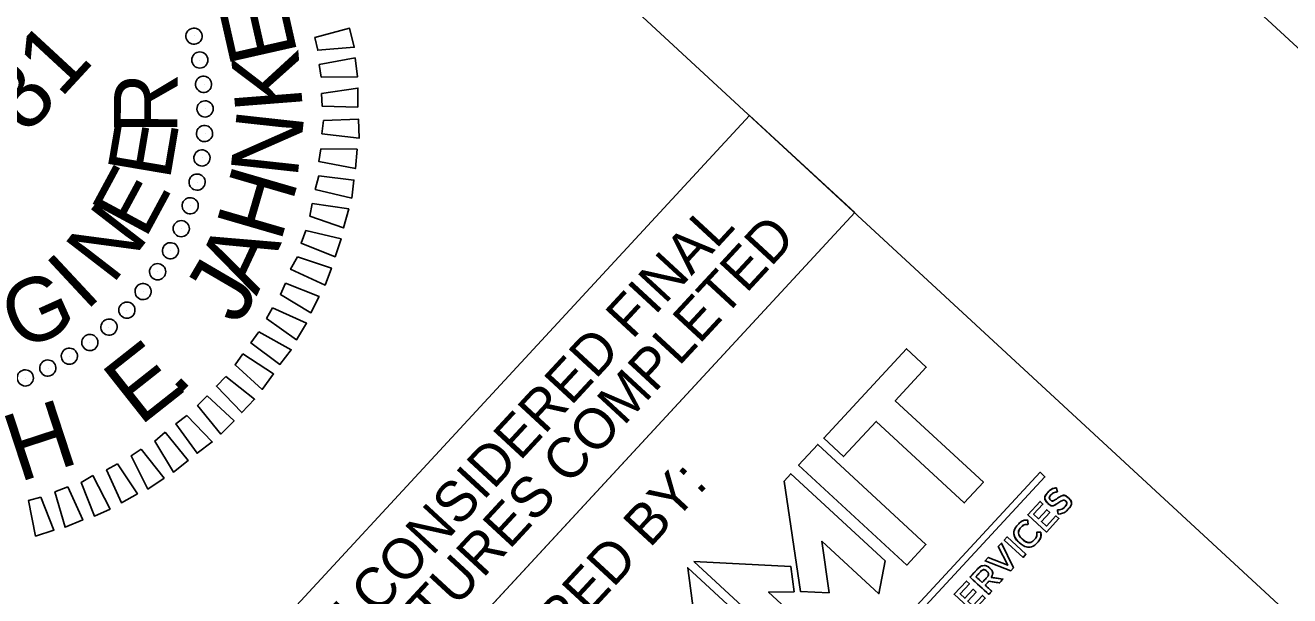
# Model space of a CAD drawing. Extents: x 1768064 to 1770025, y 999327 to 1001342.
# Drawn here: x 1769319.3 to 1769431.7, y 1001074.7 to 1001125.4 of the extents above; entities that cross this region are included whole.
import ezdxf

# ---------------------------------------------------------------- set-up
doc = ezdxf.new("R2010")
doc.units = 0
for name, color, linetype in [('_CIVIL_CONSTRUCTION', 7, 'Continuous'), ('E_NCDOT_Terrain_Model_Flow_Arrows', 7, 'Continuous'), ('E_NCDOT_Terrain_Model_Spot_Elevation', 7, 'Continuous'), ('P_NCDOT_Horizontal_Alignment_Station_Major_Label', 7, 'Continuous'), ('P_NCDOT_Horizontal_Alignment_Tick_Large', 7, 'Continuous')]:
    doc.layers.add(name, color=color, linetype=linetype)

msp = doc.modelspace()

# ---------------------------------------------------------------- linework, layer by layer
at = {"layer": '_CIVIL_CONSTRUCTION'}
msp.add_lwpolyline([(1768063.72, 1000073.53), (1769217.66, 1001321.9), (1770025.42, 1000575.24), (1768871.49, 999326.87)], close=True, dxfattribs=at)
at = {"layer": 'E_NCDOT_Terrain_Model_Flow_Arrows'}
msp.add_line((1770025.42, 1000575.24), (1769217.66, 1001321.9), dxfattribs=at)
at = {"layer": 'E_NCDOT_Terrain_Model_Spot_Elevation'}
msp.add_line((1769972.42, 1000573.14), (1769219.74, 1001268.91), dxfattribs=at)
at = {"layer": 'P_NCDOT_Horizontal_Alignment_Station_Major_Label'}
for p, q in [((1769393.04, 1001108.72), (1769325.2, 1001035.33)), ((1769411.06, 1001083.89), (1769410.97, 1001084.25)), ((1769410.45, 1001083.17), (1769410.44, 1001083.17)), ((1769411.79, 1001083.06), (1769411.79, 1001083.06)), ((1769412.03, 1001083.36), (1769412.02, 1001083.37)), ((1769410.21, 1001082.87), (1769410.21, 1001082.86)), ((1769411.06, 1001082.28), (1769411.11, 1001081.91)), ((1769408.46, 1001081), (1769408.41, 1001081.38)), ((1769407.94, 1001079.67), (1769407.94, 1001079.67)), ((1769409.59, 1001080.31), (1769409.23, 1001080.31)), ((1769407.67, 1001079.37), (1769407.67, 1001079.37)), ((1769404.78, 1001076.83), (1769404.78, 1001076.82)), ((1769405.03, 1001077.12), (1769405.02, 1001077.13))]:
    msp.add_line(p, q, dxfattribs=at)
msp.add_lwpolyline([(1769315.85, 1001043.97), (1769383.69, 1001117.36), (1769393.04, 1001108.72), (1769325.2, 1001035.33)], close=True, dxfattribs=at)
for points in [[(1769397.63, 1001096.61), (1769399.4, 1001094.97), (1769396.65, 1001091.99), (1769404.48, 1001084.75), (1769402.78, 1001082.91), (1769394.95, 1001090.15), (1769392.06, 1001087.03), (1769390.29, 1001088.67), (1769397.63, 1001096.61)], [(1769390.29, 1001088.67), (1769392.06, 1001087.03), (1769394.95, 1001090.15), (1769402.78, 1001082.91), (1769404.48, 1001084.75), (1769396.65, 1001091.99), (1769399.4, 1001094.97), (1769397.63, 1001096.61), (1769390.29, 1001088.67)], [(1769388.06, 1001086.26), (1769389.76, 1001088.1), (1769399.37, 1001079.22), (1769397.67, 1001077.38), (1769388.06, 1001086.26)], [(1769397.67, 1001077.38), (1769399.37, 1001079.22), (1769389.76, 1001088.1), (1769388.06, 1001086.26), (1769397.67, 1001077.38)], [(1769409.95, 1001085.22), (1769368.67, 1001040.57), (1769368.23, 1001040.98), (1769409.51, 1001085.63), (1769409.95, 1001085.22)], [(1769409.51, 1001085.63), (1769368.23, 1001040.98), (1769368.67, 1001040.57), (1769409.95, 1001085.22), (1769409.51, 1001085.63)], [(1769386.76, 1001084.85), (1769388.23, 1001075.02), (1769390.77, 1001074.91), (1769390.13, 1001079.5), (1769395.2, 1001074.82), (1769395.74, 1001077.76), (1769387.36, 1001085.5), (1769386.76, 1001084.85)], [(1769386.76, 1001084.85), (1769388.23, 1001075.02), (1769390.77, 1001074.91), (1769390.13, 1001079.5), (1769395.2, 1001074.82), (1769395.74, 1001077.76), (1769387.36, 1001085.5), (1769386.76, 1001084.85)], [(1769408.42, 1001081.85), (1769409.51, 1001083.04), (1769409.77, 1001082.8), (1769408.94, 1001081.89), (1769409.37, 1001081.49), (1769410.11, 1001082.29), (1769410.37, 1001082.05), (1769409.63, 1001081.25), (1769410.08, 1001080.84), (1769410.93, 1001081.75), (1769411.19, 1001081.51), (1769410.08, 1001080.31), (1769408.42, 1001081.85)], [(1769410.08, 1001080.31), (1769411.19, 1001081.51), (1769410.93, 1001081.75), (1769410.08, 1001080.84), (1769409.63, 1001081.25), (1769410.37, 1001082.05), (1769410.11, 1001082.29), (1769409.37, 1001081.49), (1769408.94, 1001081.89), (1769409.77, 1001082.8), (1769409.51, 1001083.04), (1769408.42, 1001081.85), (1769410.08, 1001080.31)], [(1769406.33, 1001079.6), (1769406.59, 1001079.88), (1769408.26, 1001078.34), (1769408, 1001078.06), (1769406.33, 1001079.6)], [(1769408, 1001078.06), (1769408.26, 1001078.34), (1769406.59, 1001079.88), (1769406.33, 1001079.6), (1769408, 1001078.06)], [(1769404.63, 1001077.75), (1769404.91, 1001078.06), (1769406.64, 1001077.36), (1769405.8, 1001079.03), (1769406.08, 1001079.33), (1769407.15, 1001077.12), (1769406.92, 1001076.87), (1769404.63, 1001077.75)], [(1769406.92, 1001076.87), (1769407.15, 1001077.12), (1769406.08, 1001079.33), (1769405.8, 1001079.03), (1769406.64, 1001077.36), (1769404.91, 1001078.06), (1769404.63, 1001077.75), (1769406.92, 1001076.87)], [(1769378.74, 1001077.7), (1769390.44, 1001066.89), (1769392.14, 1001068.73), (1769385.39, 1001074.97), (1769387.66, 1001075), (1769387.37, 1001077.25), (1769378.74, 1001077.7)], [(1769378.74, 1001077.7), (1769390.44, 1001066.89), (1769392.14, 1001068.73), (1769385.39, 1001074.97), (1769387.66, 1001075), (1769387.37, 1001077.25), (1769378.74, 1001077.7)], [(1769378.21, 1001077.14), (1769389.91, 1001066.32), (1769388.21, 1001064.48), (1769381.46, 1001070.72), (1769381.62, 1001068.46), (1769379.34, 1001068.57), (1769378.21, 1001077.14)], [(1769379.34, 1001068.57), (1769381.62, 1001068.46), (1769381.46, 1001070.72), (1769388.21, 1001064.48), (1769389.91, 1001066.32), (1769378.21, 1001077.14), (1769379.34, 1001068.57)], [(1769403.95, 1001077.02), (1769403.29, 1001076.31), (1769404.96, 1001074.77), (1769405.22, 1001075.05), (1769404.64, 1001075.59), (1769404.96, 1001075.94), (1769405.91, 1001075.79), (1769406.21, 1001076.13), (1769405.18, 1001076.28)], [(1769404.76, 1001076.24), (1769404.38, 1001075.83), (1769403.82, 1001076.34), (1769404.19, 1001076.75)], [(1769401.88, 1001074.78), (1769402.97, 1001075.96), (1769403.23, 1001075.72), (1769402.4, 1001074.82), (1769402.83, 1001074.42), (1769403.57, 1001075.22), (1769403.83, 1001074.98), (1769403.09, 1001074.17), (1769403.54, 1001073.76), (1769404.39, 1001074.68), (1769404.65, 1001074.43), (1769403.54, 1001073.24), (1769401.88, 1001074.78)], [(1769403.54, 1001073.24), (1769404.65, 1001074.43), (1769404.39, 1001074.68), (1769403.54, 1001073.76), (1769403.09, 1001074.17), (1769403.83, 1001074.98), (1769403.57, 1001075.22), (1769402.83, 1001074.42), (1769402.4, 1001074.82), (1769403.23, 1001075.72), (1769402.97, 1001075.96), (1769401.88, 1001074.78), (1769403.54, 1001073.24)]]:
    msp.add_lwpolyline(points, dxfattribs=at)
for points, degree in [([(1769410.97, 1001084.25), (1769410.69, 1001084.21), (1769410.44, 1001084.09), (1769410.23, 1001083.86), (1769409.93, 1001083.54), (1769409.92, 1001083.13), (1769410.21, 1001082.87)], 3), ([(1769411.11, 1001081.91), (1769411.11, 1001081.91), (1769411.06, 1001082.28), (1769411.06, 1001082.28), (1769411.34, 1001082.3), (1769411.56, 1001082.38), (1769411.74, 1001082.58), (1769411.9, 1001082.75), (1769411.92, 1001082.94), (1769411.79, 1001083.06), (1769411.79, 1001083.06), (1769411.79, 1001083.06), (1769411.79, 1001083.06), (1769411.67, 1001083.17), (1769411.55, 1001083.17), (1769411.2, 1001082.94), (1769410.8, 1001082.68), (1769410.52, 1001082.58), (1769410.21, 1001082.86), (1769410.21, 1001082.86), (1769410.21, 1001082.87), (1769410.21, 1001082.87), (1769409.92, 1001083.13), (1769409.93, 1001083.54), (1769410.23, 1001083.86), (1769410.44, 1001084.09), (1769410.69, 1001084.21), (1769410.97, 1001084.25), (1769410.97, 1001084.25), (1769411.06, 1001083.89), (1769411.06, 1001083.89), (1769410.81, 1001083.85), (1769410.62, 1001083.76), (1769410.48, 1001083.62), (1769410.33, 1001083.45), (1769410.33, 1001083.28), (1769410.44, 1001083.17), (1769410.44, 1001083.17), (1769410.45, 1001083.17), (1769410.45, 1001083.17), (1769410.57, 1001083.05), (1769410.7, 1001083.07), (1769411.06, 1001083.31), (1769411.46, 1001083.57), (1769411.74, 1001083.62), (1769412.02, 1001083.37), (1769412.02, 1001083.37), (1769412.03, 1001083.36), (1769412.03, 1001083.36), (1769412.34, 1001083.08), (1769412.31, 1001082.67), (1769412, 1001082.33), (1769411.77, 1001082.09), (1769411.47, 1001081.94), (1769411.11, 1001081.91)], 3), ([(1769410.21, 1001082.86), (1769410.52, 1001082.58), (1769410.8, 1001082.68), (1769411.2, 1001082.94), (1769411.55, 1001083.17), (1769411.67, 1001083.17), (1769411.79, 1001083.06)], 3), ([(1769410.44, 1001083.17), (1769410.33, 1001083.28), (1769410.33, 1001083.45), (1769410.48, 1001083.62), (1769410.62, 1001083.76), (1769410.81, 1001083.85), (1769411.06, 1001083.89)], 3), ([(1769412.02, 1001083.37), (1769411.74, 1001083.62), (1769411.46, 1001083.57), (1769411.06, 1001083.31), (1769410.7, 1001083.07), (1769410.57, 1001083.05), (1769410.45, 1001083.17)], 3), ([(1769411.79, 1001083.06), (1769411.92, 1001082.94), (1769411.9, 1001082.75), (1769411.74, 1001082.58), (1769411.56, 1001082.38), (1769411.34, 1001082.3), (1769411.06, 1001082.28)], 3), ([(1769411.11, 1001081.91), (1769411.47, 1001081.94), (1769411.77, 1001082.09), (1769412, 1001082.33), (1769412.31, 1001082.67), (1769412.34, 1001083.08), (1769412.03, 1001083.36)], 3), ([(1769407.67, 1001079.37), (1769407.67, 1001079.37), (1769407.67, 1001079.37), (1769407.67, 1001079.37), (1769407.19, 1001079.81), (1769407.12, 1001080.51), (1769407.57, 1001080.99), (1769407.84, 1001081.29), (1769408.11, 1001081.37), (1769408.41, 1001081.38), (1769408.41, 1001081.38), (1769408.46, 1001081), (1769408.46, 1001081), (1769408.21, 1001080.99), (1769408, 1001080.93), (1769407.84, 1001080.74), (1769407.55, 1001080.44), (1769407.61, 1001079.97), (1769407.94, 1001079.67), (1769407.94, 1001079.67), (1769407.94, 1001079.67), (1769407.94, 1001079.67), (1769408.27, 1001079.37), (1769408.74, 1001079.34), (1769409.02, 1001079.65), (1769409.2, 1001079.84), (1769409.24, 1001080.05), (1769409.23, 1001080.31), (1769409.23, 1001080.31), (1769409.59, 1001080.31), (1769409.59, 1001080.31), (1769409.61, 1001079.98), (1769409.56, 1001079.69), (1769409.28, 1001079.39), (1769408.85, 1001078.92), (1769408.15, 1001078.93), (1769407.67, 1001079.37)], 3), ([(1769408.41, 1001081.38), (1769408.11, 1001081.37), (1769407.84, 1001081.29), (1769407.57, 1001080.99), (1769407.12, 1001080.51), (1769407.19, 1001079.81), (1769407.67, 1001079.37)], 3), ([(1769407.94, 1001079.67), (1769407.61, 1001079.97), (1769407.55, 1001080.44), (1769407.84, 1001080.74), (1769408, 1001080.93), (1769408.21, 1001080.99), (1769408.46, 1001081)], 3), ([(1769407.67, 1001079.37), (1769408.15, 1001078.93), (1769408.85, 1001078.92), (1769409.28, 1001079.39), (1769409.56, 1001079.69), (1769409.61, 1001079.98), (1769409.59, 1001080.31)], 3), ([(1769409.23, 1001080.31), (1769409.24, 1001080.05), (1769409.2, 1001079.84), (1769409.02, 1001079.65), (1769408.74, 1001079.34), (1769408.27, 1001079.37), (1769407.94, 1001079.67)], 3), ([(1769403.29, 1001076.31), (1769403.29, 1001076.31), (1769403.95, 1001077.02), (1769403.95, 1001077.02), (1769404.14, 1001077.22), (1769404.34, 1001077.32), (1769404.54, 1001077.33), (1769404.71, 1001077.33), (1769404.88, 1001077.26), (1769405.02, 1001077.13), (1769405.02, 1001077.13), (1769405.03, 1001077.12), (1769405.03, 1001077.12), (1769405.3, 1001076.87), (1769405.32, 1001076.56), (1769405.18, 1001076.28), (1769405.18, 1001076.28), (1769406.21, 1001076.13), (1769406.21, 1001076.13), (1769406.21, 1001076.13), (1769405.91, 1001075.79), (1769405.91, 1001075.79), (1769405.91, 1001075.79), (1769404.96, 1001075.94), (1769404.96, 1001075.94), (1769404.96, 1001075.94), (1769404.64, 1001075.59), (1769404.64, 1001075.59), (1769404.64, 1001075.59), (1769405.22, 1001075.05), (1769405.22, 1001075.05), (1769405.22, 1001075.05), (1769404.96, 1001074.77), (1769404.96, 1001074.77), (1769404.96, 1001074.77), (1769403.29, 1001076.31), (1769403.29, 1001076.31)], 3), ([(1769405.02, 1001077.13), (1769404.88, 1001077.26), (1769404.71, 1001077.33), (1769404.54, 1001077.33), (1769404.34, 1001077.32), (1769404.14, 1001077.22), (1769403.95, 1001077.02)], 3), ([(1769404.76, 1001076.24), (1769404.94, 1001076.44), (1769404.95, 1001076.67), (1769404.78, 1001076.82), (1769404.78, 1001076.82), (1769404.78, 1001076.83), (1769404.78, 1001076.83), (1769404.6, 1001076.99), (1769404.39, 1001076.96), (1769404.19, 1001076.75), (1769404.19, 1001076.75), (1769403.82, 1001076.34), (1769403.82, 1001076.34), (1769403.82, 1001076.34), (1769404.38, 1001075.83), (1769404.38, 1001075.83), (1769404.38, 1001075.83), (1769404.76, 1001076.24), (1769404.76, 1001076.24)], 3), ([(1769404.19, 1001076.75), (1769404.39, 1001076.96), (1769404.6, 1001076.99), (1769404.78, 1001076.83)], 2), ([(1769404.78, 1001076.82), (1769404.95, 1001076.67), (1769404.94, 1001076.44), (1769404.76, 1001076.24)], 2), ([(1769405.18, 1001076.28), (1769405.32, 1001076.56), (1769405.3, 1001076.87), (1769405.03, 1001077.12)], 2)]:
    msp.add_open_spline(points, degree=degree, dxfattribs=at)
at = {"layer": 'P_NCDOT_Horizontal_Alignment_Tick_Large'}
for p, q in [((1769334.38, 1001124.43), (1769334.38, 1001124.43)), ((1769334.85, 1001122.29), (1769334.85, 1001122.29)), ((1769335.22, 1001120.11), (1769335.22, 1001120.11)), ((1769335.34, 1001117.96), (1769335.34, 1001117.96)), ((1769335.32, 1001115.73), (1769335.32, 1001115.73)), ((1769335.05, 1001113.59), (1769335.05, 1001113.59)), ((1769334.6, 1001111.42), (1769334.6, 1001111.42)), ((1769334.01, 1001109.31), (1769334.01, 1001109.31)), ((1769333.24, 1001107.29), (1769333.24, 1001107.29)), ((1769332.26, 1001105.35), (1769332.26, 1001105.35)), ((1769331.06, 1001103.46), (1769331.06, 1001103.46)), ((1769329.82, 1001101.68), (1769329.82, 1001101.68)), ((1769328.36, 1001100.03), (1769328.36, 1001100.03)), ((1769326.76, 1001098.51), (1769326.76, 1001098.51)), ((1769325.04, 1001097.17), (1769325.04, 1001097.17)), ((1769323.29, 1001095.93), (1769323.29, 1001095.93)), ((1769321.35, 1001094.87), (1769321.35, 1001094.87)), ((1769319.33, 1001094.01), (1769319.33, 1001094.01))]:
    msp.add_line(p, q, dxfattribs=at)
for points in [[(1769345.07, 1001124.28), (1769348.15, 1001125.11), (1769348.57, 1001123.43), (1769345.32, 1001123.16)], [(1769345.44, 1001121.89), (1769348.64, 1001122.48), (1769348.85, 1001120.79), (1769345.63, 1001120.77)], [(1769345.65, 1001119.32), (1769348.89, 1001119.8), (1769348.88, 1001118.1), (1769345.7, 1001118.19)], [(1769345.82, 1001116.92), (1769348.93, 1001117.04), (1769348.99, 1001115.34), (1769345.69, 1001115.74)], [(1769345.6, 1001114.4), (1769348.82, 1001114.35), (1769348.67, 1001112.64), (1769345.43, 1001113.26)], [(1769345.41, 1001111.98), (1769348.54, 1001111.61), (1769348.35, 1001110.01), (1769345.1, 1001110.77)], [(1769344.83, 1001109.52), (1769348.07, 1001109.05), (1769347.61, 1001107.36), (1769344.63, 1001108.41)], [(1769344.26, 1001107.13), (1769347.4, 1001106.4), (1769346.86, 1001104.79), (1769343.84, 1001106.01)], [(1769343.53, 1001104.8), (1769346.54, 1001103.78), (1769345.97, 1001102.28), (1769342.9, 1001103.68)], [(1769342.46, 1001102.46), (1769345.44, 1001101.26), (1769344.72, 1001099.82), (1769342, 1001101.45)], [(1769341.31, 1001100.25), (1769344.33, 1001098.88), (1769343.43, 1001097.4), (1769340.78, 1001099.31)], [(1769340.08, 1001098.12), (1769342.97, 1001096.53), (1769341.96, 1001095.22), (1769339.38, 1001097.13)], [(1769338.67, 1001096.15), (1769341.39, 1001094.38), (1769340.39, 1001093), (1769337.97, 1001095.17)], [(1769337.16, 1001094.14), (1769339.71, 1001092.12), (1769338.56, 1001090.94), (1769336.31, 1001093.3)], [(1769335.49, 1001092.42), (1769337.88, 1001090.21), (1769336.72, 1001089.03), (1769334.64, 1001091.57)], [(1769333.69, 1001090.68), (1769335.94, 1001088.33), (1769334.6, 1001087.32), (1769332.72, 1001089.94)], [(1769331.76, 1001089.19), (1769333.81, 1001086.69), (1769332.5, 1001085.65), (1769330.84, 1001088.41)], [(1769329.63, 1001087.69), (1769331.67, 1001085.12), (1769330.23, 1001084.14), (1769328.73, 1001087.09)], [(1769327.52, 1001086.37), (1769329.29, 1001083.72), (1769327.87, 1001082.92), (1769326.55, 1001085.84)], [(1769325.33, 1001085.33), (1769326.87, 1001082.35), (1769325.47, 1001081.73), (1769324.3, 1001084.72)], [(1769323.11, 1001084.32), (1769324.43, 1001081.4), (1769322.86, 1001080.74), (1769321.96, 1001083.89)], [(1769320.7, 1001083.41), (1769321.88, 1001080.49), (1769320.24, 1001079.96), (1769319.62, 1001083.12)]]:
    msp.add_lwpolyline(points, close=True, dxfattribs=at)
for centre, major_axis in [((1769334.32, 1001124.41), (0.691, 0.201)), ((1769334.84, 1001122.29), (0.706, 0.14)), ((1769335.17, 1001120.13), (0.716, 0.078)), ((1769335.31, 1001117.94), (0.72, 0.016)), ((1769335.26, 1001115.75), (0.718, -0.047)), ((1769335.03, 1001113.58), (0.712, -0.11)), ((1769334.6, 1001111.43), (0.699, -0.171)), ((1769333.99, 1001109.33), (0.682, -0.231)), ((1769333.19, 1001107.29), (0.659, -0.29)), ((1769332.23, 1001105.33), (0.631, -0.346)), ((1769331.09, 1001103.46), (0.599, -0.4)), ((1769329.8, 1001101.7), (0.562, -0.451)), ((1769328.36, 1001100.05), (0.52, -0.498)), ((1769326.77, 1001098.54), (0.475, -0.541)), ((1769325.07, 1001097.17), (0.426, -0.581)), ((1769323.25, 1001095.95), (0.374, -0.616)), ((1769321.33, 1001094.9), (0.318, -0.646)), ((1769319.33, 1001094.02), (0.261, -0.671))]:
    msp.add_ellipse(centre, major_axis=major_axis, ratio=0.999708, dxfattribs=at)

# ---------------------------------------------------------------- texts
at = {"layer": 'P_NCDOT_Horizontal_Alignment_Station_Major_Label'}
for s, height, p in [('DOCUMENT NOT CONSIDERED FINAL', 3.5982, (1769323.01, 1001042.99)), ('UNLESS ALL SIGNATURES COMPLETED', 3.5982, (1769324.78, 1001038.05)), ('PLANS PREPARED BY:', 3.5979, (1769344.34, 1001045.84))]:
    msp.add_text(s, height=height, rotation=47.2512, dxfattribs=at).set_placement(p)
at = {"layer": 'P_NCDOT_Horizontal_Alignment_Tick_Large'}
for s, height, rotation, p in [('E', 6, 102.7443, (1769343.56, 1001122.82)), ('046981', 5.998, 47.2512, (1769307.31, 1001102.43)), ('K', 6, 94.4603, (1769344, 1001117.96)), ('R', 5.64, 89.7326, (1769332.84, 1001115.7)), ('E', 5.64, 80.3753, (1769332.16, 1001111.5)), ('N', 6, 83.7345, (1769343.51, 1001111.67)), ('E', 5.64, 61.663, (1769329.99, 1001106.28)), ('H', 6, 73.7505, (1769342.01, 1001105.98)), ('N', 5.64, 52.3076, (1769327.07, 1001102.24)), ('A', 6, 64.9102, (1769339.88, 1001101.24)), ('I', 5.64, 42.9524, (1769324.69, 1001099.88)), ('J', 6, 59.6524, (1769338.28, 1001098.59)), ('G', 5.64, 24.2415, (1769318.85, 1001096.36)), ('E', 6, 38.3089, (1769329.51, 1001089.67)), ('.', 6, 45.4183, (1769332.79, 1001092.27)), ('H', 6, 18.1246, (1769318.76, 1001084.72))]:
    msp.add_text(s, height=height, rotation=rotation, dxfattribs=at).set_placement(p)

doc.saveas('drawing.dxf')
